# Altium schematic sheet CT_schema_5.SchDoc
size 293 x 258 mm
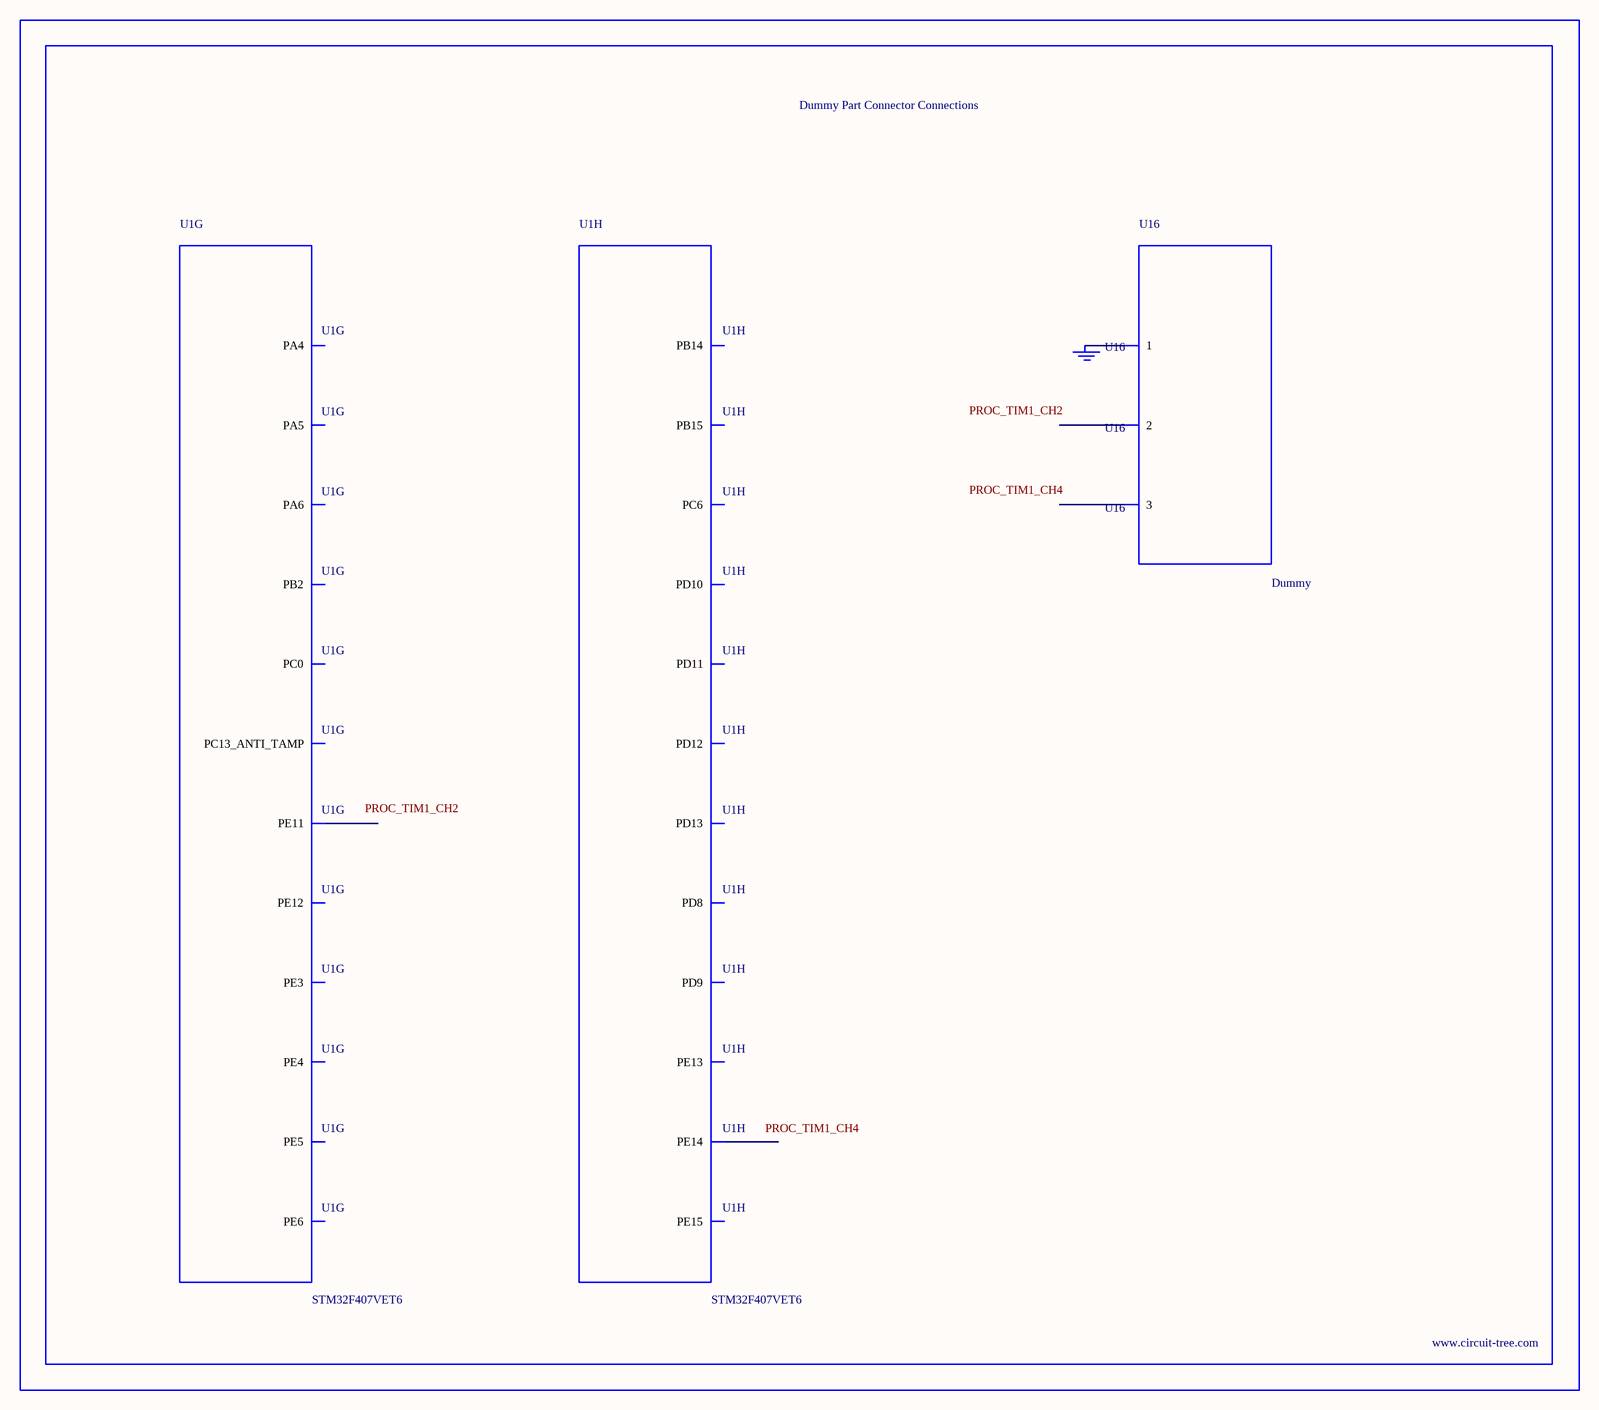
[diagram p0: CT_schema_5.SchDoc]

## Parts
BORDER4  (no value)
GND_INSTANCE_4_0  (no value)
U1  STM32F407VET6  [LQFP100]  (parts G,H of 8)
U16  Dummy  [DUMMY_PACKAGE_218]

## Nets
NetGND_INSTANCE_4_0_0: GND_INSTANCE_4_0.0(GND) U16.1

Not connected (* = marked no-connect by the designer): U1 2(PE3) 3(PE4) 4(PE5) 5(PE6) 7(PC13_ANTI_TAMP) 15(PC0) 29(PA4) 30(PA5) 31(PA6) 37(PB2) 42(PE11) 43(PE12) 44(PE13) 45(PE14) 46(PE15) 53(PB14) 54(PB15) 55(PD8) 56(PD9) 57(PD10) 58(PD11) 59(PD12) 60(PD13) 63(PC6); U16 2 3

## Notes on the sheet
- Labels drawn without touching a wire or pin: PROC_TIM1_CH2, PROC_TIM1_CH4

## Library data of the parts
BORDER4 = BORDER_PAGE4
GND_INSTANCE_4_0 = GND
